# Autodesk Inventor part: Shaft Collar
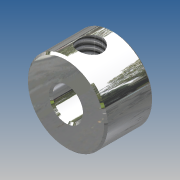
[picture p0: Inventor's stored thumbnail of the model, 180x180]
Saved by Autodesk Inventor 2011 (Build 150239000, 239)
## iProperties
Created: 2010-06
Part Number: Shaft Collar
Document SubType Name: Modeling
Designer: Phil
Density: 1 g/cm^3
Author: Phil
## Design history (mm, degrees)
sketch "Sketch1"
  geometry: C1 r 5.499 at (0, 0); 1 further point
  constraints: 1 centre point, 1 coincident
  dimensions: "d0" = 10.9982 diameter of C1
extrude "Extrusion1" new body sketch "Sketch1" distance "d1" = 6.604; taper "d2" = 0 deg
chamfer "Chamfer1" distance "d3" = 0.254; stored, may be unused: second distance "d4" = 3.175, angle "d5" = 45 deg
sketch "Sketch2"
  geometry: C1 r 5.245 at (0, 0) reference
hole "Hole1" sketch "Sketch2" at (0, 0) diameter "d6" = 4.191; stored, may be unused: countersink angle "d10" = 82 deg, drill point angle "d12" = 118 deg; dims "d7" = 19.05, "d8" = 9.525, "d9" = 6.35, "d11" = 25.4
workplane "Work Plane1"
sketch "Sketch3"
  geometry: L1 (-5.245, 0)-(5.245, 0) reference; L2 (5.499, -0.254)-(5.499, -6.35) reference; 2 further points
hole "Hole2" sketch "Sketch3" at (0, -3.302) diameter "d13" = 3.302; stored, may be unused: countersink angle "d17" = 82 deg, drill point angle "d19" = 118 deg; dims "d14" = 19.05, "d15" = 9.525, "d16" = 6.35, "d18" = 25.4
chamfer "Chamfer2" distance "d20" = 0.254; stored, may be unused: second distance "d21" = 3.175, angle "d22" = 45 deg
body "Solid1"
